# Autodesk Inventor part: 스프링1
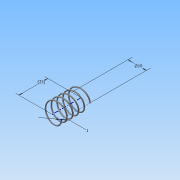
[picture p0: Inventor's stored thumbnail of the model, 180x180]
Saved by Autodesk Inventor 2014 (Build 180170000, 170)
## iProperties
Created: 2015-06
Part Number: 스프링1
Material: Generic
Document SubType Name: Modeling
Designer: Administrator
Density: 1 g/cm^3
Appearance: Default
Author: Administrator
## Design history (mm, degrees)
sketch "스케치1"
  geometry: L1 (0, 0)-(8, 0); L2 (8, 0)-(8, 21.5); L3 (8, 21.5)-(0, 21.5); L4 (0, 21.5)-(0, 0); C1 r 0.5 at (8, 0)
  constraints: 8 end point, 2 parallel, 1 centre point, 1 coincident, 1 horizontal, 1 perpendicular
  dimensions: "d0" = 21.5 distance of L3.end L1.start (derived); "d1" = 16 diameter of L2 L4; "d2" = 1 diameter of C1
feature "코일1" sketch "스케치1" pitch "d3" = 10; turns "d5" = 5; dims "d4" = 21.5 (= d0), "d6" = 0, angle "d7" = 90 deg, angle "d8" = 90 deg, "d9" = 0, "d10" = 0
sketch "스케치2"
  geometry: L1 (-8.5, 0)-(-7.5, 0) reference; 1 further point
  constraints: 1 horizontal alignment
extrude "돌출1" cut sketch "스케치2" stored distance "d11" = 10; taper "d12" = 0 deg
node "작업 평면1"
sketch "스케치3"
  geometry: L1 (-7.5, 0)-(-8.5, 0) reference; 1 further point
  constraints: 1 horizontal alignment
extrude "돌출2" cut sketch "스케치3" stored distance "d14" = 10; taper "d15" = 0 deg
node "솔리드1"
node "절단 모서리 투영1"
node "절단 모서리 투영2"
other parameters: "d13" = 21.5 (= d0)
